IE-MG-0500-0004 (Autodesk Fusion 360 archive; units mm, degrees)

design "IS-MG-0400-0005" references "3M Screw", "POWER", "Digitus_DN-651107_LAN-Switch 19.5mm", "LED", "4 ports ethernet", "1 ethernet port"
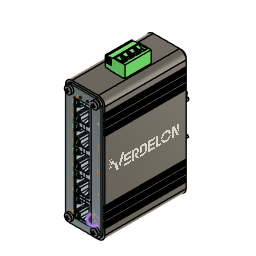
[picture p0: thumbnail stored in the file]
sketch "Sketch1" plane through (0, 0, 0) normal (0, 1, 0) x axis (1, 0, 0)
  line L1 (25, 0) -> (5, 0)
  line L2 (30, -90) -> (30, -5)
  line L3 (5, -95) -> (25, -95)
  line L4 (0, -5) -> (0, -90)
  arc A1 centre (5, -90) radius 5 clockwise from (5, -95) to (0, -90)
  arc A2 centre (25, -90) radius 5 clockwise from (30, -90) to (25, -95)
  arc A3 centre (5, -5) radius 5 clockwise from (0, -5) to (5, 0)
  arc A4 centre (25, -5) radius 5 clockwise from (25, 0) to (30, -5)
  point P1 (0, 0)
  point P2 (0, 0)
  point P4 (0, -95)
  point P3 (30, 0)
  horizontal L1
  vertical L2
  horizontal L3
  vertical L4
  coincident P1 P2
  coincident P4 L3
  coincident P4 L4
  tangent L3 A1
  tangent L4 A1
  tangent L2 A2
  tangent L3 A2
  equal A1 A2
  coincident P2 L1
  coincident P2 L4
  tangent L1 A3
  tangent L4 A3
  equal A1 A3
  coincident P3 L1
  coincident P3 L2
  tangent L1 A4
  tangent L2 A4
  equal A1 A4
  dimension "d1" distance P2 P4 = 95
  dimension "d2" distance P2 P3 = 30
  dimension "d3" radius A1 = 5
extrude "Extrude1" new body sketch "Sketch1" along normal blind 65
sketch "Sketch2" plane through (0, 0, 0) normal (0, -1, 0) x axis (1, 0, 0)
  line L1 (5, 95) -> (25, 95)
  line L2 (0, 5) -> (0, 90)
  line L3 (25, 0) -> (5, 0)
  line L4 (30, 90) -> (30, 5)
  line L5 (1.5, 5) -> (1.5, 90)
  line L6 (25, 1.5) -> (5, 1.5)
  line L7 (28.5, 90) -> (28.5, 5)
  line L8 (5, 93.5) -> (25, 93.5)
  line L9 (0, 5) -> (0, 90)
  line L10 (25, 0) -> (5, 0)
  line L11 (30, 90) -> (30, 5)
  line L12 (5, 95) -> (25, 95)
  arc A1 centre (25, 90) radius 5 clockwise from (25, 95) to (30, 90)
  arc A2 centre (5, 90) radius 5 clockwise from (0, 90) to (5, 95)
  arc A3 centre (5, 5) radius 5 clockwise from (5, 0) to (0, 5)
  arc A4 centre (25, 5) radius 5 clockwise from (30, 5) to (25, 0)
  arc A5 centre (5, 5) radius 3.5 clockwise from (5, 1.5) to (1.5, 5)
  arc A6 centre (25, 5) radius 3.5 clockwise from (28.5, 5) to (25, 1.5)
  arc A7 centre (25, 90) radius 3.5 clockwise from (25, 93.5) to (28.5, 90)
  arc A8 centre (5, 90) radius 3.5 clockwise from (1.5, 90) to (5, 93.5)
  arc A9 centre (5, 5) radius 5 clockwise from (5, 0) to (0, 5)
  arc A10 centre (25, 5) radius 5 clockwise from (30, 5) to (25, 0)
  arc A11 centre (25, 90) radius 5 clockwise from (25, 95) to (30, 90)
  arc A12 centre (5, 90) radius 5 clockwise from (0, 90) to (5, 95)
  dimension "d6" = -1.5
  dimension "d7" distance L2 = 0
extrude "Extrude2" cut sketch "Sketch2" against normal blind 1.5
sketch "Sketch3" plane through (0, 65, 0) normal (0, 1, 0) x axis (-1, 0, 0)
  line L1 (-30, 5) -> (-30, 90)
  line L2 (-5, 0) -> (-25, 0)
  line L3 (0, 90) -> (0, 5)
  line L4 (-25, 95) -> (-5, 95)
  line L5 (-28.5, 5) -> (-28.5, 90)
  line L6 (-5, 1.5) -> (-25, 1.5)
  line L7 (-1.5, 90) -> (-1.5, 5)
  line L8 (-25, 93.5) -> (-5, 93.5)
  line L9 (-30, 5) -> (-30, 90)
  line L10 (-5, 0) -> (-25, 0)
  line L11 (0, 90) -> (0, 5)
  line L12 (-25, 95) -> (-5, 95)
  arc A1 centre (-25, 90) radius 5 clockwise from (-30, 90) to (-25, 95)
  arc A2 centre (-25, 5) radius 5 clockwise from (-25, 0) to (-30, 5)
  arc A3 centre (-5, 5) radius 5 clockwise from (0, 5) to (-5, 0)
  arc A4 centre (-5, 90) radius 5 clockwise from (-5, 95) to (0, 90)
  arc A5 centre (-25, 5) radius 3.5 clockwise from (-25, 1.5) to (-28.5, 5)
  arc A6 centre (-5, 5) radius 3.5 clockwise from (-1.5, 5) to (-5, 1.5)
  arc A7 centre (-5, 90) radius 3.5 clockwise from (-5, 93.5) to (-1.5, 90)
  arc A8 centre (-25, 90) radius 3.5 clockwise from (-28.5, 90) to (-25, 93.5)
  arc A9 centre (-25, 5) radius 5 clockwise from (-25, 0) to (-30, 5)
  arc A10 centre (-5, 5) radius 5 clockwise from (0, 5) to (-5, 0)
  arc A11 centre (-5, 90) radius 5 clockwise from (-5, 95) to (0, 90)
  arc A12 centre (-25, 90) radius 5 clockwise from (-30, 90) to (-25, 95)
  dimension "d10" = -1.5
  dimension "d11" distance L1 = 0
extrude "Extrude3" cut sketch "Sketch3" against normal blind 1.5
sketch "Sketch4" plane through (0, 1.5, 0) normal (0, -1, 0) x axis (1, 0, 0)
  line L1 (25, 93.5) -> (5, 93.5)
  line L2 (28.5, 5) -> (28.5, 90)
  line L3 (5, 1.5) -> (25, 1.5)
  line L4 (1.5, 90) -> (1.5, 5)
  line L5 (0, 5) -> (0, 90)
  line L6 (25, 0) -> (5, 0)
  line L7 (30, 90) -> (30, 5)
  line L8 (5, 95) -> (25, 95)
  line L9 (-15.934, 47.5) -> (1.5, 47.5)
  line L10 (15, 105) -> (15, 93.5)
  line L11 (0.5, 85.5) -> (0, 85.5)
  line L12 (0.5, 84.5) -> (0.5, 85.5)
  line L13 (0, 84.5) -> (0.5, 84.5)
  line L14 (0, 85.5) -> (0, 84.5)
  line L15 (0, 84) -> (0, 83)
  line L16 (0, 83) -> (0.5, 83)
  line L17 (0.5, 84) -> (0, 84)
  line L18 (0.5, 83) -> (0.5, 84)
  line L19 (0, 82.5) -> (0, 81.5)
  line L20 (0, 81.5) -> (0.5, 81.5)
  line L21 (0.5, 82.5) -> (0, 82.5)
  line L22 (0.5, 81.5) -> (0.5, 82.5)
  line L23 (0, 79) -> (0.5, 79)
  line L24 (0, 77) -> (0, 76)
  line L25 (0, 78.5) -> (0, 77.5)
  line L26 (0.5, 78.5) -> (0, 78.5)
  line L27 (0.5, 80) -> (0, 80)
  line L28 (0, 76) -> (0.5, 76)
  line L29 (0.5, 76) -> (0.5, 77)
  line L30 (0, 80) -> (0, 79)
  line L31 (0.5, 77) -> (0, 77)
  line L32 (0, 77.5) -> (0.5, 77.5)
  line L33 (0.5, 77.5) -> (0.5, 78.5)
  line L34 (0.5, 79) -> (0.5, 80)
  line L35 (0, 73.5) -> (0.5, 73.5)
  line L36 (0, 71.5) -> (0, 70.5)
  line L37 (0, 73) -> (0, 72)
  line L38 (0.5, 73) -> (0, 73)
  line L39 (0.5, 74.5) -> (0, 74.5)
  line L40 (0, 70.5) -> (0.5, 70.5)
  line L41 (0.5, 70.5) -> (0.5, 71.5)
  line L42 (0, 74.5) -> (0, 73.5)
  line L43 (0.5, 71.5) -> (0, 71.5)
  line L44 (0, 72) -> (0.5, 72)
  line L45 (0.5, 72) -> (0.5, 73)
  line L46 (0.5, 73.5) -> (0.5, 74.5)
  line L47 (0, 23.5) -> (0, 24.5)
  line L48 (0.5, 17.5) -> (0.5, 16.5)
  line L49 (0.5, 19) -> (0.5, 18)
  line L50 (0, 20.5) -> (0, 21.5)
  line L51 (0, 16) -> (0.5, 16)
  line L52 (0.5, 11) -> (0, 11)
  line L53 (0.5, 12) -> (0.5, 11)
  line L54 (0, 12) -> (0.5, 12)
  line L55 (0.5, 15) -> (0, 15)
  line L56 (0, 15) -> (0, 16)
  line L57 (0, 17.5) -> (0.5, 17.5)
  line L58 (0, 19) -> (0.5, 19)
  line L59 (0.5, 16) -> (0.5, 15)
  line L60 (0, 11) -> (0, 12)
  line L61 (0, 22) -> (0, 23)
  line L62 (0.5, 18) -> (0, 18)
  line L63 (0, 13.5) -> (0.5, 13.5)
  line L64 (0.5, 23) -> (0.5, 22)
  line L65 (0.5, 10.5) -> (0.5, 9.5)
  line L66 (0, 10.5) -> (0.5, 10.5)
  line L67 (0.5, 23.5) -> (0, 23.5)
  line L68 (0.5, 12.5) -> (0, 12.5)
  line L69 (0.5, 21.5) -> (0.5, 20.5)
  line L70 (0.5, 16.5) -> (0, 16.5)
  line L71 (0, 12.5) -> (0, 13.5)
  line L72 (0, 16.5) -> (0, 17.5)
  line L73 (0, 24.5) -> (0.5, 24.5)
  line L74 (0.5, 24.5) -> (0.5, 23.5)
  line L75 (0, 21.5) -> (0.5, 21.5)
  line L76 (0.5, 9.5) -> (0, 9.5)
  line L77 (0.5, 13.5) -> (0.5, 12.5)
  line L78 (0, 9.5) -> (0, 10.5)
  line L79 (0, 18) -> (0, 19)
  line L80 (0.5, 22) -> (0, 22)
  line L81 (0.5, 20.5) -> (0, 20.5)
  line L82 (0, 23) -> (0.5, 23)
  line L83 (30, 76) -> (29.5, 76)
  line L84 (30, 70.5) -> (29.5, 70.5)
  line L85 (29.5, 73.5) -> (29.5, 74.5)
  line L86 (30, 84.5) -> (29.5, 84.5)
  line L87 (30, 73) -> (30, 72)
  line L88 (30, 83) -> (29.5, 83)
  line L89 (30, 72) -> (29.5, 72)
  line L90 (30, 73.5) -> (29.5, 73.5)
  line L91 (29.5, 83) -> (29.5, 84)
  line L92 (29.5, 77) -> (30, 77)
  line L93 (30, 71.5) -> (30, 70.5)
  line L94 (30, 78.5) -> (30, 77.5)
  line L95 (29.5, 73) -> (30, 73)
  line L96 (29.5, 82.5) -> (30, 82.5)
  line L97 (30, 81.5) -> (29.5, 81.5)
  line L98 (29.5, 84) -> (30, 84)
  line L99 (29.5, 77.5) -> (29.5, 78.5)
  line L100 (30, 79) -> (29.5, 79)
  line L101 (29.5, 84.5) -> (29.5, 85.5)
  line L102 (30, 77) -> (30, 76)
  line L103 (30, 74.5) -> (30, 73.5)
  line L104 (29.5, 79) -> (29.5, 80)
  line L105 (29.5, 81.5) -> (29.5, 82.5)
  line L106 (30, 80) -> (30, 79)
  line L107 (29.5, 85.5) -> (30, 85.5)
  line L108 (30, 85.5) -> (30, 84.5)
  line L109 (29.5, 76) -> (29.5, 77)
  line L110 (30, 84) -> (30, 83)
  line L111 (29.5, 71.5) -> (30, 71.5)
  line L112 (29.5, 78.5) -> (30, 78.5)
  line L113 (29.5, 70.5) -> (29.5, 71.5)
  line L114 (30, 82.5) -> (30, 81.5)
  line L115 (29.5, 80) -> (30, 80)
  line L116 (29.5, 74.5) -> (30, 74.5)
  line L117 (30, 77.5) -> (29.5, 77.5)
  line L118 (29.5, 72) -> (29.5, 73)
  line L119 (30, 17.5) -> (29.5, 17.5)
  line L120 (29.5, 23.5) -> (30, 23.5)
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  point P22 (1.5, 47.5)
  point P24 (15, 93.5)
  point P26 (0, 85.5)
  point P81 (0, 9.5)
  point P27 (0.5, 85.5)
  point P73 (0.5, 9.5)
  point P28 (0.5, 84.5)
  point P67 (0.5, 10.5)
  point P29 (0, 84.5)
  point P89 (0, 10.5)
  point P30 (0, 83)
  point P91 (0, 12)
  point P31 (0, 84)
  point P86 (0, 11)
  point P32 (0.5, 83)
  point P65 (0.5, 12)
  point P33 (0.5, 84)
  point P77 (0.5, 11)
  point P34 (0, 81.5)
  point P70 (0, 13.5)
  point P35 (0, 82.5)
  point P68 (0, 12.5)
  point P36 (0.5, 81.5)
  point P80 (0.5, 13.5)
  point P37 (0.5, 82.5)
  point P82 (0.5, 12.5)
  point P38 (0, 79)
  point P83 (0, 16)
  point P39 (0.5, 79)
  point P76 (0.5, 16)
  point P40 (0.5, 80)
  point P74 (0.5, 15)
  point P41 (0, 76)
  point P71 (0, 19)
  point P42 (0, 77)
  point P62 (0, 18)
  point P43 (0.5, 77)
  point P63 (0.5, 18)
  point P44 (0, 77.5)
  point P93 (0, 17.5)
  point P45 (0, 78.5)
  point P92 (0, 16.5)
  point P46 (0.5, 78.5)
  point P90 (0.5, 16.5)
  point P47 (0, 80)
  point P96 (0, 15)
  point P48 (0.5, 76)
  point P95 (0.5, 19)
  point P49 (0.5, 77.5)
  point P97 (0.5, 17.5)
  point P50 (0, 73.5)
  point P87 (0, 21.5)
  point P51 (0.5, 73.5)
  point P88 (0.5, 21.5)
  point P52 (0.5, 74.5)
  point P94 (0.5, 20.5)
  point P53 (0, 70.5)
  point P66 (0, 24.5)
  point P54 (0, 71.5)
  point P64 (0, 23.5)
  point P55 (0.5, 71.5)
  point P78 (0.5, 23.5)
  point P56 (0, 72)
  point P72 (0, 23)
  point P57 (0, 73)
  point P75 (0, 22)
  point P58 (0.5, 73)
  point P69 (0.5, 22)
  point P59 (0, 74.5)
  point P79 (0, 20.5)
  point P60 (0.5, 70.5)
  point P84 (0.5, 24.5)
  point P61 (0.5, 72)
  point P85 (0.5, 23)
  point P106 (30, 85.5)
  point P121 (29.5, 85.5)
  point P122 (29.5, 84.5)
  point P118 (30, 84.5)
  point P120 (30, 83)
  point P119 (30, 84)
  point P123 (29.5, 83)
  point P126 (29.5, 84)
  point P125 (30, 81.5)
  point P124 (30, 82.5)
  point P100 (29.5, 81.5)
  point P98 (29.5, 82.5)
  point P102 (30, 79)
  point P99 (29.5, 79)
  point P101 (29.5, 80)
  point P131 (30, 76)
  point P129 (30, 77)
  point P127 (29.5, 77)
  point P130 (30, 77.5)
  point P133 (30, 78.5)
  point P128 (29.5, 78.5)
  point P132 (30, 80)
  point P113 (29.5, 76)
  point P116 (29.5, 77.5)
  point P112 (30, 73.5)
  point P117 (29.5, 73.5)
  point P115 (29.5, 74.5)
  point P114 (30, 70.5)
  point P111 (30, 71.5)
  point P105 (29.5, 71.5)
  point P108 (30, 72)
  point P104 (30, 73)
  point P103 (29.5, 73)
  point P109 (30, 74.5)
  point P110 (29.5, 70.5)
  point P107 (29.5, 72)
  point P169 (30, 18)
  point P134 (29.5, 18)
  point P138 (30, 23.5)
  point P166 (29.5, 12)
  point P139 (30, 24.5)
  point P160 (29.5, 10.5)
  point P140 (30, 12.5)
  point P135 (29.5, 22)
  point P147 (30, 13.5)
  point P136 (30, 19)
  point P155 (30, 23)
  point P148 (29.5, 9.5)
  point P162 (29.5, 15)
  point P168 (30, 22)
  point P157 (29.5, 16)
  point P141 (29.5, 11)
  point P165 (29.5, 23.5)
  point P167 (30, 20.5)
  point P151 (29.5, 13.5)
  point P143 (30, 9.5)
  point P152 (29.5, 12.5)
  point P150 (30, 16)
  point P145 (29.5, 24.5)
  point P142 (29.5, 23)
  point P164 (30, 11)
  point P149 (30, 21.5)
  point P146 (29.5, 21.5)
  point P154 (30, 10.5)
  point P144 (29.5, 16.5)
  point P153 (30, 12)
  point P158 (30, 16.5)
  point P156 (30, 17.5)
  point P163 (29.5, 20.5)
  point P161 (29.5, 19)
  point P159 (30, 15)
  point P137 (29.5, 17.5)
  midpoint L4 P22
  perpendicular L4 L9
  midpoint L1 P24
  perpendicular L8 L10
  horizontal L11
  vertical L12
  horizontal L13
  vertical L14
  coincident L5 P26
  symmetric L9 P26 P81
  symmetric L9 P27 P73
  symmetric L9 P28 P67
  symmetric L9 P29 P89
  symmetric L9 P30 P91
  symmetric L9 P31 P86
  symmetric L9 P32 P65
  symmetric L9 P33 P77
  symmetric L9 P34 P70
  symmetric L9 P35 P68
  symmetric L9 P36 P80
  symmetric L9 P37 P82
  symmetric L9 P38 P83
  symmetric L9 P39 P76
  symmetric L9 P40 P74
  symmetric L9 P41 P71
  symmetric L9 P42 P62
  symmetric L9 P43 P63
  symmetric L9 P44 P93
  symmetric L9 P45 P92
  symmetric L9 P46 P90
  symmetric L9 P47 P96
  symmetric L9 P48 P95
  symmetric L9 P49 P97
  symmetric L9 P50 P87
  symmetric L9 P51 P88
  symmetric L9 P52 P94
  symmetric L9 P53 P66
  symmetric L9 P54 P64
  symmetric L9 P55 P78
  symmetric L9 P56 P72
  symmetric L9 P57 P75
  symmetric L9 P58 P69
  symmetric L9 P59 P79
  symmetric L9 P60 P84
  symmetric L9 P61 P85
  symmetric L10 P26 P106
  symmetric L10 P27 P121
  symmetric L10 P28 P122
  symmetric L10 P29 P118
  symmetric L10 P30 P120
  symmetric L10 P31 P119
  symmetric L10 P32 P123
  symmetric L10 P33 P126
  symmetric L10 P34 P125
  symmetric L10 P35 P124
  symmetric L10 P36 P100
  symmetric L10 P37 P98
  symmetric L10 P38 P102
  symmetric L10 P39 P99
  symmetric L10 P40 P101
  symmetric L10 P41 P131
  symmetric L10 P42 P129
  symmetric L10 P43 P127
  symmetric L10 P44 P130
  symmetric L10 P45 P133
  symmetric L10 P46 P128
  symmetric L10 P47 P132
  symmetric L10 P48 P113
  symmetric L10 P49 P116
  symmetric L10 P50 P112
  symmetric L10 P51 P117
  symmetric L10 P52 P115
  symmetric L10 P53 P114
  symmetric L10 P54 P111
  symmetric L10 P55 P105
  symmetric L10 P56 P108
  symmetric L10 P57 P104
  symmetric L10 P58 P103
  symmetric L10 P59 P109
  symmetric L10 P60 P110
  symmetric L10 P61 P107
  symmetric L10 P62 P169
  symmetric L10 P63 P134
  symmetric L10 P64 P138
  symmetric L10 P65 P166
  symmetric L10 P66 P139
  symmetric L10 P67 P160
  symmetric L10 P68 P140
  symmetric L10 P69 P135
  symmetric L10 P70 P147
  symmetric L10 P71 P136
  symmetric L10 P72 P155
  symmetric L10 P73 P148
  symmetric L10 P74 P162
  symmetric L10 P75 P168
  symmetric L10 P76 P157
  symmetric L10 P77 P141
  symmetric L10 P78 P165
  symmetric L10 P79 P167
  symmetric L10 P80 P151
  symmetric L10 P81 P143
  symmetric L10 P82 P152
  symmetric L10 P83 P150
  symmetric L10 P84 P145
  symmetric L10 P85 P142
  symmetric L10 P86 P164
  symmetric L10 P87 P149
  symmetric L10 P88 P146
  symmetric L10 P89 P154
  symmetric L10 P90 P144
  symmetric L10 P91 P153
  symmetric L10 P92 P158
  symmetric L10 P93 P156
  symmetric L10 P94 P163
  symmetric L10 P95 P161
  symmetric L10 P96 P159
  symmetric L10 P97 P137
  dimension "d14" distance P26 P29 = 1
  dimension "d15" distance P26 P27 = 0.5
  dimension "d24" distance L9 L40 = 23
  dimension "d18" R-Pattern1-uDistance = 0
  dimension "d19" R-Pattern1-vDistance = -3
  dimension "d22" R-Pattern2-uDistance = 0
  dimension "d23" R-Pattern2-vDistance = -11
extrude "Extrude4" cut sketch "Sketch4" against normal blind 64
sketch "Sketch5" plane through (0, 0, 0) normal (0, -1, 0) x axis (1, 0, 0)
  line L1 (5, 93.5) -> (25, 93.5)
  line L2 (1.5, 5) -> (1.5, 90)
  line L3 (25, 1.5) -> (5, 1.5)
  line L4 (28.5, 90) -> (28.5, 5)
  line L5 (15, 47.5) -> (15, 93.5)
  line L6 (21.16, 86.4) -> (8, 86.4)
  line L7 (21.16, 6.65) -> (21.16, 86.4)
  line L8 (8, 6.65) -> (21.16, 6.65)
  line L9 (8, 86.4) -> (8, 6.65)
  line L10 (5, 6) -> (5, 1.5)
  line L11 (5, 6) -> (1.5, 6)
  arc A1 centre (5, 90) radius 3.5 clockwise from (1.5, 90) to (5, 93.5)
  arc A2 centre (5, 5) radius 3.5 clockwise from (5, 1.5) to (1.5, 5)
  arc A3 centre (25, 5) radius 3.5 clockwise from (28.5, 5) to (25, 1.5)
  arc A4 centre (25, 90) radius 3.5 clockwise from (25, 93.5) to (28.5, 90)
  circle C1 centre (13, 88.4) radius 0.75
  circle C2 centre (18.3333, 88.4) radius 0.75
  circle C3 centre (5, 6) radius 1.5
  circle C4 centre (25, 6) radius 1.5
  circle C5 centre (5, 90) radius 1.5
  circle C6 centre (25, 90) radius 1.5
  circle C7 centre (23.16, 13) radius 0.75
  point P14 (15, 93.5)
  point P7 (5, 1.5)
  point P22 (5, 1.5)
  point P23 (1.5, 6)
  point P24 (5, 6)
  point P25 (5, 6)
  point P16 (8, 86.4)
  point P19 (8, 6.65)
  point P17 (21.16, 86.4)
  point P20 (13, 88.4)
  point P29 (23.16, 13)
  midpoint L1 P14
  perpendicular L1 L5
  horizontal L6
  vertical L7
  horizontal L8
  vertical L9
  coincident P7 P22
  perpendicular L3 L10
  coincident L2 P23
  perpendicular L10 L11
  coincident P24 P25
  dimension "d33" distance P16 P19 = 79.75
  dimension "d34" distance P16 P17 = 13.16
  dimension "d35" distance L5 L9 = 7
  dimension "d38" diameter C1 = 1.5
  dimension "d39" distance L6 P20 = 2
  dimension "d44" distance L9 P20 = 5
  dimension "d105" diameter C7 = 1.5
  dimension "d106" distance L7 P29 = 2
  dimension "d42" R-Pattern2-uDistance = 8
  dimension "d43" R-Pattern2-vDistance = 0
  dimension "d81" R-Pattern2-uDistance = 20
  dimension "d82" R-Pattern2-vDistance = 0
  dimension "d85" R-Pattern3-uDistance = 0
  dimension "d86" R-Pattern3-vDistance = 84
extrude "Extrude5" cut sketch "Sketch5" profile of L6 L7 L8 L9 C1 C2 L10 L11 C3 C4 C5 C6 C7 against normal blind 2
shell "Shell1" innerThickness 1
sketch "Sketch6" plane through (0, 0, 95) normal (0, 0, 1) x axis (-1, 0, 0)
  line L1 (-5, -63.5) -> (-25, -63.5)
  line L2 (-5, -1.5) -> (-5, -63.5)
  line L3 (-25, -1.5) -> (-5, -1.5)
  line L4 (-25, -63.5) -> (-25, -1.5)
  line L5 (-15, -32.5) -> (-15, -63.5)
  line L6 (-15, -32.5) -> (-5, -32.5)
  line L7 (-23.17, -42.5) -> (-15.5, -42.5)
  line L8 (-23.17, -22.5) -> (-23.17, -42.5)
  line L9 (-15.5, -22.5) -> (-23.17, -22.5)
  line L10 (-15.5, -42.5) -> (-15.5, -22.5)
  point P6 (-15, -63.5)
  point P7 (-5, -32.5)
  point P10 (-23.17, -42.5)
  point P11 (-23.17, -22.5)
  point P9 (-15.5, -42.5)
  midpoint L1 P6
  perpendicular L1 L5
  midpoint L2 P7
  perpendicular L5 L6
  horizontal L7
  vertical L8
  horizontal L9
  vertical L10
  symmetric L6 L7 L9
  dimension "d48" distance P10 P11 = 20
  dimension "d49" distance P9 P10 = 7.67
  dimension "d50" distance L5 L10 = 0.5
extrude "Extrude6" cut sketch "Sketch6" profile of L7 L8 L9 L10 against normal blind 5
component_insert "Component Insert3"
joint "Assemble1" alignAngle 0 alignOffsetX 0 alignOffsetY 0 alignOffsetZ 2.25
rectangular_pattern "00000000-0000-0000-0000-000000000000" uSpaceDistance 10.7 vSpaceDistance 0
component_insert "Component Insert7"
component_insert "Component Insert10"
position "Position2"
component_insert "Component Insert14"
joint "Assemble3" alignAngle -90 alignOffsetX 0 alignOffsetY 0 alignOffsetZ 11.95
rectangular_pattern "00000000-0000-0000-0000-000000000000" uSpaceDistance 20 vSpaceDistance 0
rectangular_pattern "00000000-0000-0000-0000-000000000000" uSpaceDistance -84 vSpaceDistance 0
component_insert "Component Insert17"
component_insert "Component Insert18"
position "Position3"
sketch "Sketch10" plane through (0, 0, 0) normal (0, -1, 0) x axis (1, 0, 0)
  dimension "d107" = 1
  dimension "d108" = 1
  dimension "d109" = 1
  dimension "d110" = 1
  dimension "d111" = 1
  dimension "d112" = 1
  dimension "d113" = 1
  dimension "d114" = 1
  dimension "d115" = 1
  dimension "d116" = 1
  dimension "d117" = 1
  dimension "d118" = 1
  dimension "d119" = 1
decal "Decal3"
decal "Decal4"
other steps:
joint_origin "JointOrigin1"
joint_origin "JointOrigin3"

design "POWER"
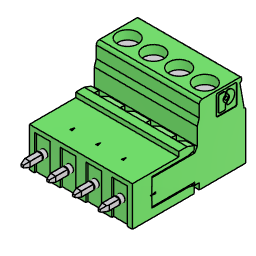
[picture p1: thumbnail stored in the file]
description: STEP AP214
part number: POWER

design "1 ethernet port"
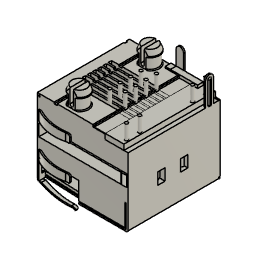
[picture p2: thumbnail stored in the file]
description: STEP AP214
part number: 1 ethernet port

design "3M Screw"
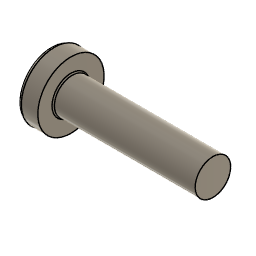
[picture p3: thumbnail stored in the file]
description: STEP AP214
part number: 3M Screw

design "4 ports ethernet"
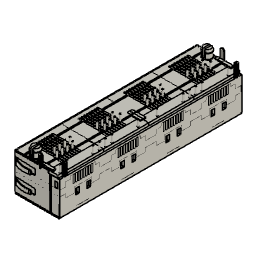
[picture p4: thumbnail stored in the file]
description: STEP AP214
part number: 4 ports ethernet

design "Digitus_DN-651107_LAN-Switch 19.5mm"
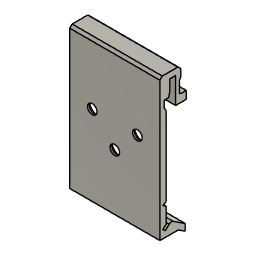
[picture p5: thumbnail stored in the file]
description: STEP AP214
part number: Digitus_DN-651107_LAN-Switch 19.5mm

design "LED"
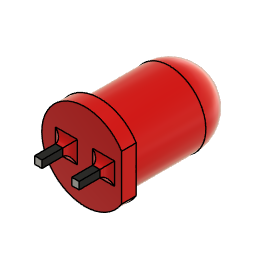
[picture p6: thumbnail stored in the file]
description: STEP AP214
part number: LED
